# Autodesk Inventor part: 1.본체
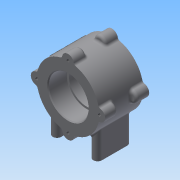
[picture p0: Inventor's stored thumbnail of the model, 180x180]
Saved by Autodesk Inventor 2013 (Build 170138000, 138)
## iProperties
Created: 2015-03
Part Number: 1.본체
Material: 일반
Document SubType Name: Modeling
Designer: Administrator
Density: 1 g/cm^3
Author: Administrator
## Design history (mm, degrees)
sketch "스케치1"
  geometry: L1 (-26, 0)-(26, 0); L2 (-25, 23.5)-(-4.3, 23.5); L3 (-4, 23.2)-(-4, 21); L4 (-4, 21)-(4, 21); L5 (4, 21)-(4, 23.2); L6 (4.3, 23.5)-(25, 23.5); L7 (26, 24.5)-(26, 37); L8 (26, 37)-(-26, 37); L9 (-26, 37)-(-26, 24.5); L10 (-25, 23.5)-(-26, 24.5); L11 (25, 23.5)-(26, 24.5); A1 r 0.3 centre (-4.3, 23.2) between (-4, 23.2) and (-4.3, 23.5); A2 r 0.3 centre (4.3, 23.2) between (4.3, 23.5) and (4, 23.2); 4 further points
  constraints: 22 end point, 6 parallel, 4 point on circle, 4 point on line, 4 tangent, 2 centre point, 2 collinear, 2 vertical alignment, 1 coincident, 1 equal radius, 1 horizontal, 1 midpoint, 1 perpendicular
  dimensions: "d1" = 52 distance of L1.start L1.end; "d3" = 42 diameter of L4 L1; "d4" = 47 diameter of L2 L1; "d5" = 22 distance between parallel lines of L3 L9; "d6" = 22 distance between parallel lines of L5 L7; "d7" = 74 diameter of L8 L1; "d8" = 0.3 radius of A1; "d9" = 1 distance of L2.start point (-26, 23.5); "d10" = 45 deg angle of L2 L10; "d11" = 1 distance of L6.end point (26, 23.5) (= d9); "d12" = 45 deg angle of L6 L11 (= d10)
revolve "회전1" sketch "스케치1" stored, may be unused: angle "d13" = 90 deg
sketch "스케치3"
  geometry: C1 r 7 at (0, 37); C2 r 7 at (-37, 0); C3 r 7 at (0, -37); C4 r 7 at (37, 0); 2 further points
  constraints: 4 centre point, 2 vertical alignment, 10 other
  dimensions: "d14" = 14 diameter of C1; "d18" = 360 deg dimension on point (0, 0) C1.centre (derived)
extrude "돌출1" join sketch "스케치3" distance "d20" = 15; taper "d21" = 0 deg
hole "구멍1" diameter "d24" = 3.459; stored, may be unused: countersink angle "d28" = 90 deg, drill point angle "d30" = 118 deg; dims "d22" = 10, "d23" = 10, "d25" = 8, "d26" = 4, "d27" = 2, "d29" = 11
sketch "스케치4"
  geometry: L1 (19, -16)-(29, -16); L2 (29, -16)-(29, -56); L3 (29, -56)-(19, -56); L4 (19, -56)-(19, -16); L5 (24, -16)-(24, -56); L6 (0, 0)-(0, -16); L7 (-19, -16)-(-29, -16); L8 (-29, -16)-(-29, -56); L9 (-29, -56)-(-19, -56); L10 (-19, -56)-(-19, -16); L11 (-24, -16)-(-24, -56)
  constraints: 22 end point, 6 symmetric about line, 3 parallel, 2 midpoint, 1 horizontal, 1 horizontal alignment, 1 perpendicular
  dimensions: "d34" = 56 distance from line of L3 L6.start; "d36" = 10 distance between parallel lines of L4 L2; "d38" = 24 distance from line of L6.start L5; "d39" = 40 distance between parallel lines of L3 L1
extrude "돌출2" join sketch "스케치4" stored distance "d40" = 40; taper "d41" = 0 deg
fillet "모깎기1" dims "d42" = 5
hole "구멍2" diameter "d45" = 4.134; stored, may be unused: countersink angle "d49" = 90 deg, drill point angle "d51" = 118 deg; dims "d46" = 6, "d47" = 4, "d48" = 2, "d50" = 8, "d57" = 10, "d58" = 10
fillet "모깎기2" dims "d52" = 3
fillet "모깎기3" dims "d53" = 3
node "작업 평면2"
  node "작업 평면1"
sketch "스케치6"
  geometry: 2 further points
  constraints: 1 coincident, 1 other
feature "엠보싱1" sketch "스케치6" dims "d1" = 52, "d3" = 42, "d4" = 47, "d5" = 22, "d6" = 22, "d7" = 74, "d8" = 0.3, "d9" = 1, "d10" = 45 deg, "d11" = 1 (= d9), "d12" = 45 deg (= d10), "d55" = 0.5, "d56" = 0
node "솔리드1"
pattern_circular "원형 패턴1" dims angle "d32" = 360 deg
mirror "대칭1"
mirror "대칭2"
mirror "대칭3"
node "작업축2"
other parameters: "d54" = 45 deg
